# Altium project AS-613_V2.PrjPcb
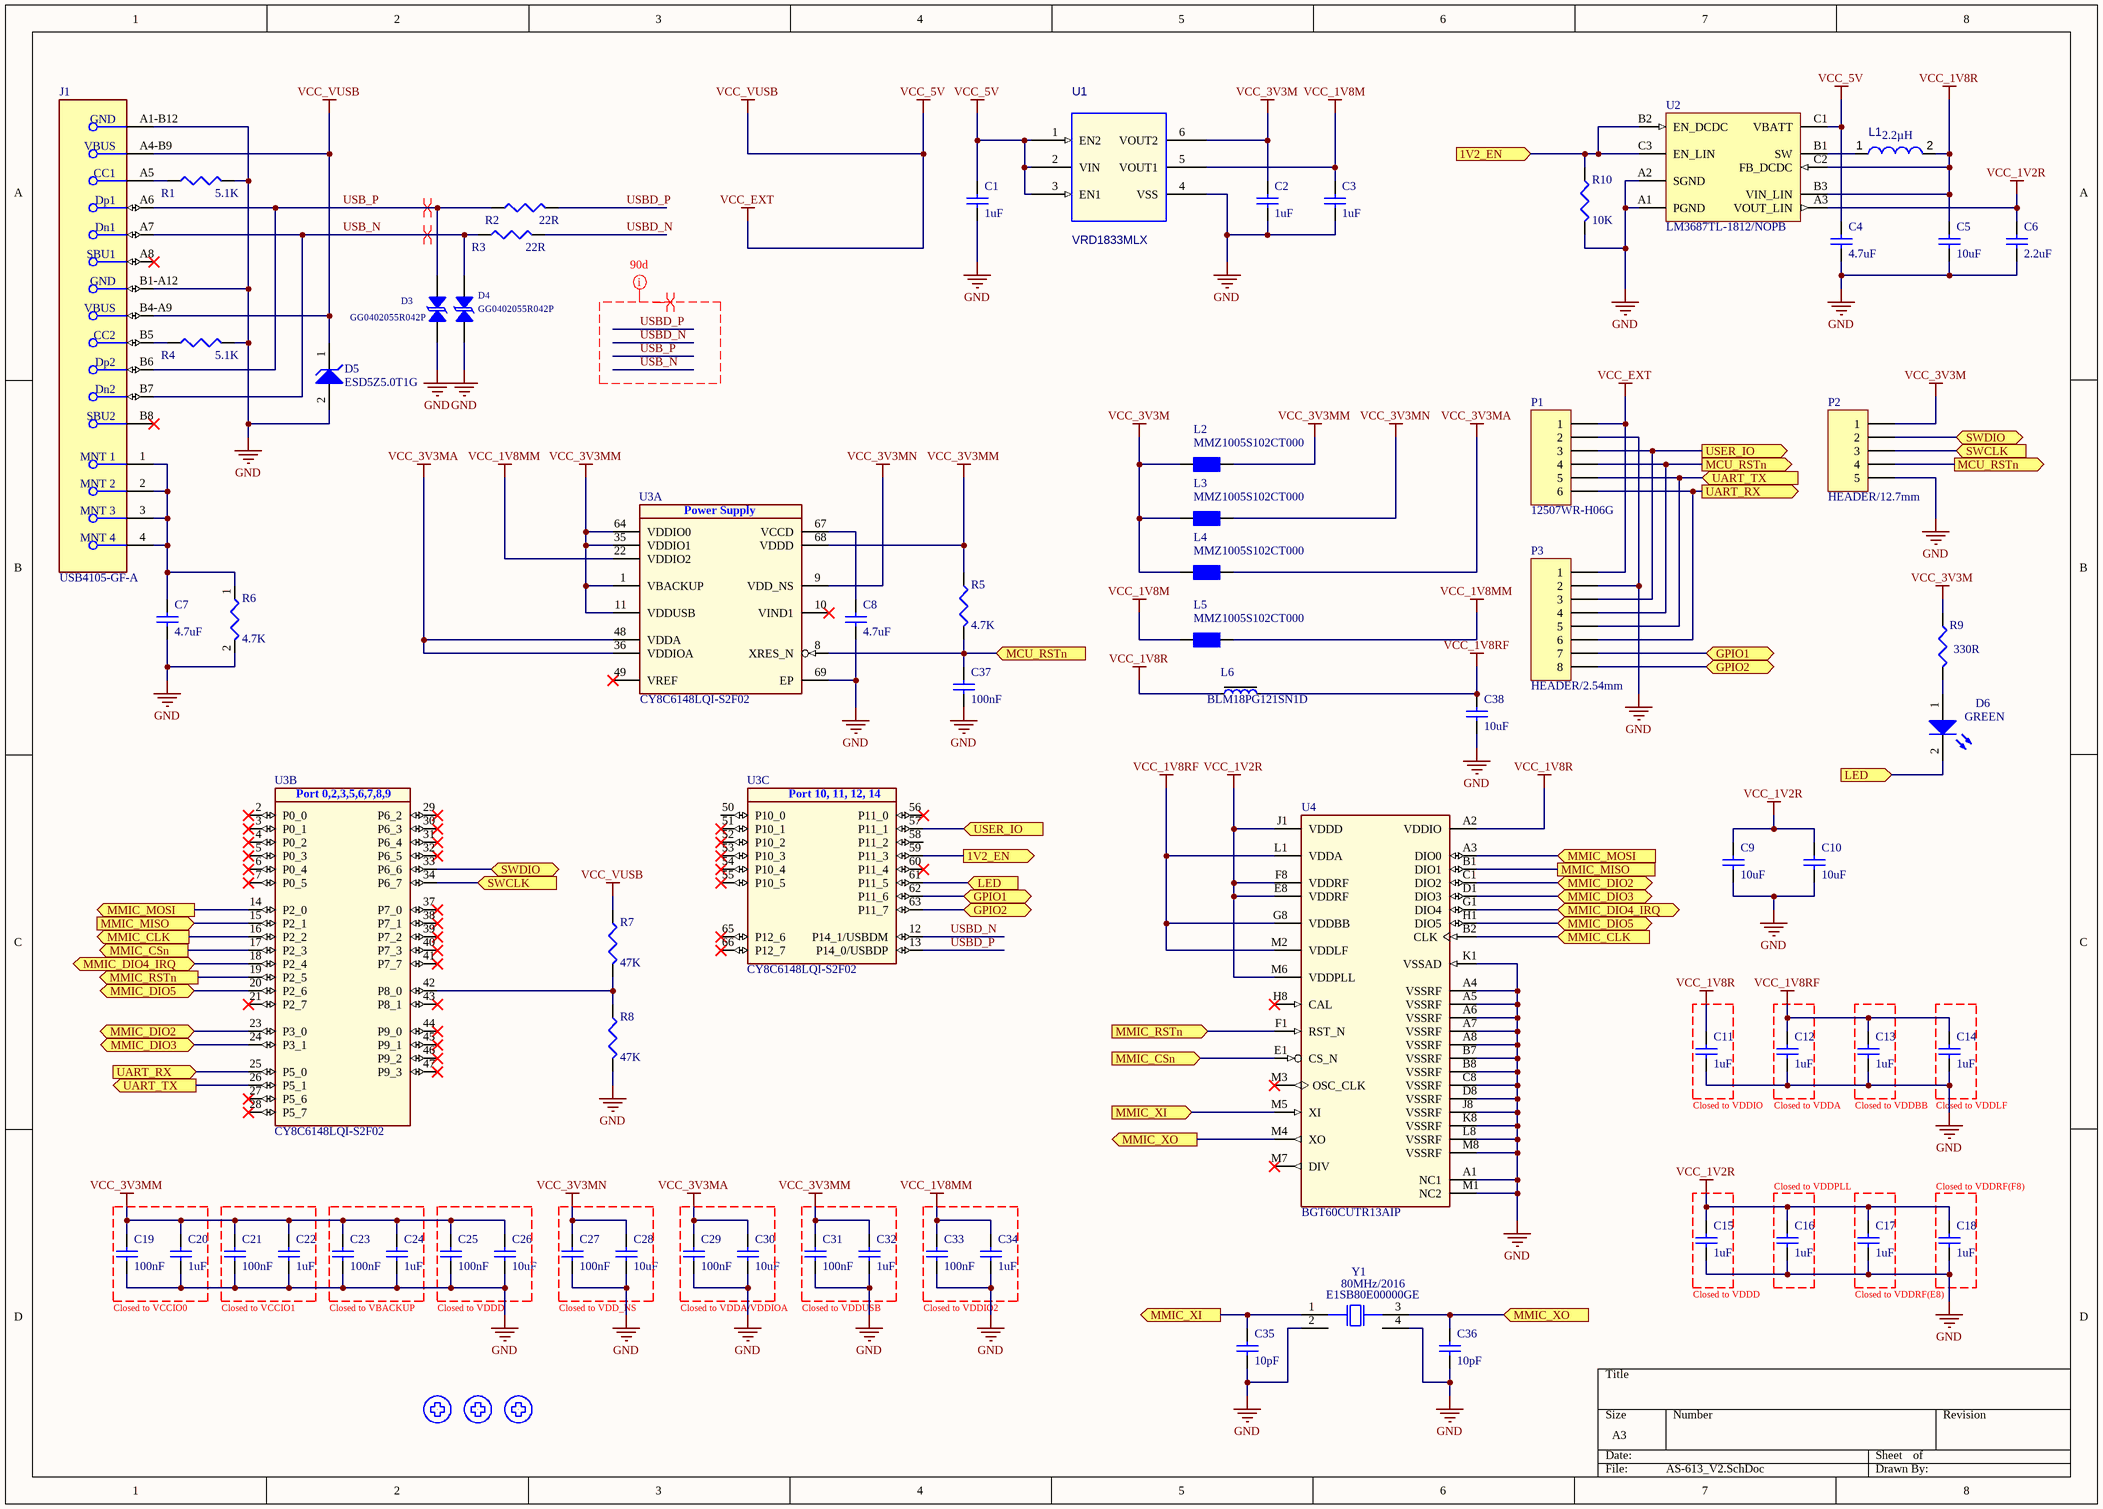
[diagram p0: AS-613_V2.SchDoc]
1 sheet, 70 parts. Net scope: flat (ports and power ports of the same name join across sheets).
Board file: AS-613V2.PcbDoc

## Sheet AS-613_V2.SchDoc
size A3; SheetNumber: 1; SheetTotal: 1; SPICEModelCacheAUYJBHOQ: <root> / <DocumentId>AUYJBHOQ</DocumentId> / <CacheFrame Number="0"> / <Model Name="cap" Kind="MDL"> / <Text>*Default semiconductor capacitor / .MODEL CAP C()</Text> / </Model> / </CacheFrame> / </root>

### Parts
C1  value 1uF  [CAP 0402/1005]  (hidden comment: Cap Semi)
C2  value 1uF  [CAP 0402/1005]  (hidden comment: Cap Semi)
C3  value 1uF  [CAP 0402/1005]  (hidden comment: Cap Semi)
C4  value 4.7uF  [CAP 0603/1608]  (hidden comment: Cap Semi)
C5  value 10uF  [CAP 0603/1608]  (hidden comment: Cap Semi)
C6  value 2.2uF  [CAP 0603/1608]  (hidden comment: Cap Semi)
C7  value 4.7uF  [CAP 0603/1608]  (hidden comment: Cap Semi)
C8  value 4.7uF  [CAP 0402/1005]  (hidden comment: Cap Semi)
C9  value 10uF  [CAP 0402/1005]  (hidden comment: Cap Semi)
C10  value 10uF  [CAP 0402/1005]  (hidden comment: Cap Semi)
C11  value 1uF  [CAP 0402/1005]  (hidden comment: Cap Semi)
C12  value 1uF  [CAP 0402/1005]  (hidden comment: Cap Semi)
C13  value 1uF  [CAP 0402/1005]  (hidden comment: Cap Semi)
C14  value 1uF  [CAP 0402/1005]  (hidden comment: Cap Semi)
C15  value 1uF  [CAP 0402/1005]  (hidden comment: Cap Semi)
C16  value 1uF  [CAP 0402/1005]  (hidden comment: Cap Semi)
C17  value 1uF  [CAP 0402/1005]  (hidden comment: Cap Semi)
C18  value 1uF  [CAP 0402/1005]  (hidden comment: Cap Semi)
C19  value 100nF  [CAP 0402/1005]  (hidden comment: Cap Semi)
C20  value 1uF  [CAP 0402/1005]  (hidden comment: Cap Semi)
C21  value 100nF  [CAP 0402/1005]  (hidden comment: Cap Semi)
C22  value 1uF  [CAP 0402/1005]  (hidden comment: Cap Semi)
C23  value 100nF  [CAP 0402/1005]  (hidden comment: Cap Semi)
C24  value 1uF  [CAP 0402/1005]  (hidden comment: Cap Semi)
C25  value 100nF  [CAP 0402/1005]  (hidden comment: Cap Semi)
C26  value 10uF  [CAP 0402/1005]  (hidden comment: Cap Semi)
C27  value 100nF  [CAP 0402/1005]  (hidden comment: Cap Semi)
C28  value 10uF  [CAP 0402/1005]  (hidden comment: Cap Semi)
C29  value 100nF  [CAP 0402/1005]  (hidden comment: Cap Semi)
C30  value 10uF  [CAP 0402/1005]  (hidden comment: Cap Semi)
C31  value 100nF  [CAP 0402/1005]  (hidden comment: Cap Semi)
C32  value 1uF  [CAP 0402/1005]  (hidden comment: Cap Semi)
C33  value 100nF  [CAP 0402/1005]  (hidden comment: Cap Semi)
C34  value 1uF  [CAP 0402/1005]  (hidden comment: Cap Semi)
C35  value 10pF  [CAP 0402/1005]  (hidden comment: Cap Semi)
C36  value 10pF  [CAP 0402/1005]  (hidden comment: Cap Semi)
C37  value 100nF  [CAP 0402/1005]  (hidden comment: Cap Semi)
C38  value 10uF  [CAP 0603/1608]  (hidden comment: Cap Semi)
D3  GG0402055R042P  [TVS 0402/1005 - BI]
D4  GG0402055R042P  [TVS 0402/1005 - BI]
D5  ESD5Z5.0T1G  [SOD523 - 21]
D6  GREEN  [LED 0603/1608 RED -21]
J1  USB4105-GF-A  [CON/ USB/ GCT_USB4105-GF-A]
L1  value 2.2µH  [IND 2520]  (hidden comment: VLS252010HBX-2R2M-1)
L2  MMZ1005S102CT000  [FER 0402/1005]
L3  MMZ1005S102CT000  [FER 0402/1005]
L4  MMZ1005S102CT000  [FER 0402/1005]
L5  MMZ1005S102CT000  [FER 0402/1005]
L6  BLM18PG121SN1D  [FER 0603/1608]
MT1  MOUNT HOLE  [MT-3 /HOLE]  (value not drawn)  (no BOM)
MT2  MOUNT HOLE  [MT-3 /HOLE]  (value not drawn)  (no BOM)
MT3  MOUNT HOLE  [MT-3 /HOLE]  (value not drawn)  (no BOM)
P1  12507WR-H06G  [12507WR-H06G]
P2  HEADER/12.7mm  [Pin Header 1x5 1.27mm]
P3  HEADER/2.54mm  [Pin Header 1x8 TH Pitch 2.54mm]
R1  value 5.1K  [RES 0402/1005]  (hidden comment: Res3)
R2  value 22R  [RES 0402/1005]  (hidden comment: Res3)
R3  value 22R  [RES 0402/1005]  (hidden comment: Res3)
R4  value 5.1K  [RES 0402/1005]  (hidden comment: Res3)
R5  value 4.7K  [RES 0402/1005]  (hidden comment: Res3)
R6  value 4.7K  [RES 0402/1005]  (hidden comment: Res3)
R7  value 47K  [RES 0402/1005]  (hidden comment: Res3)
R8  value 47K  [RES 0402/1005]  (hidden comment: Res3)
R9  value 330R  [RES 0402/1005]  (hidden comment: Res3)
R10  value 10K  [RES 0402/1005]  (hidden comment: Res3)
U1  VRD1833MLX  [LLP-6 / L2.0-W1.8-P0.50-BL-EP]
U2  LM3687TL-1812/NOPB  [DSBGA-9 / BGA50P147X147]
U3  CY8C6148LQI-S2F02  [QFN-68 /QFN40P800X800X100-69N]  (parts A,B,C of 3)
U4  BGT60CUTR13AIP  [BGT60CUTR13AIP / IFX- PG-VF2BGA-38-1]
Y1  80MHz/2016  value E1SB80E00000GE  [XTAL/2016]

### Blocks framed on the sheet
Closed to VDDPLL: C16
Closed to VDDRF(F8): C18

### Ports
1V2_EN (in), 1V2_EN (out), GPIO1 (bidir), GPIO2 (bidir), LED (in), MCU_RSTn (in), MCU_RSTn (out), MMIC_CLK (in), MMIC_CLK (out), MMIC_CSn (in), MMIC_CSn (out), MMIC_DIO2 (bidir), MMIC_DIO3 (bidir), MMIC_DIO4_IRQ (bidir), MMIC_DIO5 (bidir), MMIC_MISO, MMIC_MISO (in), MMIC_MOSI (in), MMIC_MOSI (out), MMIC_RSTn (in), MMIC_RSTn (out), MMIC_XI (in), MMIC_XI (out), MMIC_XO (in), MMIC_XO (out), SWCLK (in), SWDIO (bidir), UART_RX (in), UART_RX (out), UART_TX (in), UART_TX (out), USER_IO (in), USER_IO (out)

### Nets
GND: C1.1 C2.1 C3.1 C4.1 C5.1 C6.1 C7.1 C8.1 C9.1 C10.1 C11.1 C12.1 C13.1 C14.1 C15.1 C16.1 C17.1 C18.1 C19.1 C20.1 C21.1 C22.1 C23.1 C24.1 C25.1 C26.1 C27.1 C28.1 C29.1 C30.1 C31.1 C32.1 C33.1 C34.1 C35.1 C36.1 C37.1 C38.1 D3.1 D4.1 D5.2(A) J1.A1-B12(GND) J1.B1-A12(GND) P1.2 P2.5 P3.2 R1.2 R4.2 R6.2 R8.2 R10.2 U1.4(VSS) U2.A1(PGND) U2.A2(SGND) U3.69(EP) U4.A1(NC1) U4.A4(VSSRF) U4.A5(VSSRF) U4.A6(VSSRF) U4.A7(VSSRF) U4.A8(VSSRF) U4.B7(VSSRF) U4.B8(VSSRF) U4.C8(VSSRF) U4.D8(VSSRF) U4.J8(VSSRF) U4.K1(VSSAD) U4.K8(VSSRF) U4.L8(VSSRF) U4.M1(NC2) U4.M8(VSSRF) Y1.2 Y1.4
VCC_1V2R: C6.2 C9.2 C10.2 C15.2 C16.2 C17.2 C18.2 U2.A3(VOUT_LIN) U4.E8(VDDRF) U4.F8(VDDRF) U4.J1(VDDD) U4.M6(VDDPLL)
VCC_1V8M: C3.2 L5.1 U1.5(VOUT1)
VCC_1V8MM: C33.2 C34.2 L5.2 U3.22(VDDIO2)
VCC_1V8R: C5.2 C11.2 L1.2 L6.2 U2.B3(VIN_LIN) U2.C2(FB_DCDC) U4.A2(VDDIO)
VCC_1V8RF: C12.2 C13.2 C14.2 C38.2 L6.1 U4.G8(VDDBB) U4.L1(VDDA) U4.M2(VDDLF)
VCC_3V3M: C2.2 L2.1 L3.1 L4.1 P2.1 R9.1 U1.6(VOUT2)
VCC_3V3MA: C29.2 C30.2 L4.2 U3.36(VDDIOA) U3.48(VDDA)
VCC_3V3MM: C19.2 C20.2 C21.2 C22.2 C23.2 C24.2 C25.2 C26.2 C31.2 C32.2 L2.2 R5.1 U3.1(VBACKUP) U3.11(VDDUSB) U3.35(VDDIO1) U3.64(VDDIO0) U3.68(VDDD)
VCC_3V3MN: C27.2 C28.2 L3.2 U3.9(VDD_NS)
VCC_5V: C1.2 C4.2 D5.1(K) J1.A4-B9(VBUS) J1.B4-A9(VBUS) P1.1 P3.1 R7.1 U1.1(EN2) U1.2(VIN) U1.3(EN1) U2.C1(VBATT)  [also labelled VCC_EXT, VCC_VUSB]
1V2_EN: R10.1 U2.B2(EN_DCDC) U2.C3(EN_LIN) U3.59(P11_3) ; port 1V2_EN
GPIO1: P3.7 U3.62(P11_6) ; port GPIO1
GPIO2: P3.8 U3.63(P11_7) ; port GPIO2
LED: D6.2(K) U3.61(P11_5) ; port LED
MCU_RSTn: C37.2 P1.4 P2.4 P3.4 R5.2 U3.8(XRES_N) ; port MCU_RSTn
MMIC_CLK: U3.16(P2_2) U4.B2(CLK) ; port MMIC_CLK
MMIC_CSn: U3.17(P2_3) U4.E1(CS_N) ; port MMIC_CSn
MMIC_DIO2: U3.23(P3_0) U4.C1(DIO2) ; port MMIC_DIO2
MMIC_DIO3: U3.24(P3_1) U4.D1(DIO3) ; port MMIC_DIO3
MMIC_DIO4_IRQ: U3.18(P2_4) U4.G1(DIO4) ; port MMIC_DIO4_IRQ
MMIC_DIO5: U3.20(P2_6) U4.H1(DIO5) ; port MMIC_DIO5
MMIC_MISO: U3.15(P2_1) U4.B1(DIO1) ; port MMIC_MISO
MMIC_MOSI: U3.14(P2_0) U4.A3(DIO0) ; port MMIC_MOSI
MMIC_RSTn: U3.19(P2_5) U4.F1(RST_N) ; port MMIC_RSTn
MMIC_XI: C35.2 U4.M5(XI) Y1.1 ; port MMIC_XI
MMIC_XO: C36.2 U4.M4(XO) Y1.3 ; port MMIC_XO
SWCLK: P2.3 U3.34(P6_7) ; port SWCLK
SWDIO: P2.2 U3.33(P6_6) ; port SWDIO
UART_RX: P1.6 P3.6 U3.25(P5_0) ; port UART_RX
UART_TX: P1.5 P3.5 U3.26(P5_1) ; port UART_TX
USB_N: D4.2 J1.A7(Dn1) J1.B7(Dn2) R3.1
USB_P: D3.2 J1.A6(Dp1) J1.B6(Dp2) R2.1
USBD_N: R3.2 U3.12(P14_1/USBDM)
USBD_P: R2.2 U3.13(P14_0/USBDP)
USER_IO: P1.3 P3.3 U3.57(P11_1) ; port USER_IO
NetC7_2: C7.2 J1.1(MNT_1) J1.2(MNT_2) J1.3(MNT_3) J1.4(MNT_4) R6.1
NetC8_2: C8.2 U3.67(VCCD)
NetD6_1: D6.1(A) R9.2
NetJ1_A5: J1.A5(CC1) R1.1
NetJ1_B5: J1.B5(CC2) R4.1
NetL1_1: L1.1 U2.B1(SW)
NetR7_2: R7.2 R8.1 U3.42(P8_0)

Not connected (* = marked no-connect by the designer): J1 A8(SBU1)* B8(SBU2)*; MT1 1; MT2 1; MT3 1; U3 2(P0_0)* 3(P0_1)* 4(P0_2)* 5(P0_3)* 6(P0_4)* 7(P0_5)* 10(VIND1)* 21(P2_7)* 27(P5_6)* 28(P5_7)* 29(P6_2)* 30(P6_3)* 31(P6_4)* 32(P6_5)* 37(P7_0)* 38(P7_1)* 39(P7_2)* 40(P7_3)* 41(P7_7)* 43(P8_1)* 44(P9_0)* 45(P9_1)* 46(P9_2)* 47(P9_3)* 49(VREF)* 50(P10_0) 51(P10_1)* 52(P10_2)* 53(P10_3)* 54(P10_4)* 55(P10_5)* 56(P11_0)* 58(P11_2) 60(P11_4)* 65(P12_6)* 66(P12_7)*; U4 H8(CAL)* M3(OSC_CLK)* M7(DIV)*

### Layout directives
differential pair: USB_N, USB_P, USBD_N, USBD_P
net class 90d: USB_N, USB_P, USBD_N, USBD_P

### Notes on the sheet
- Closed to VDDIO
- Closed to VDDA
- Closed to VDDBB
- (near C14) Closed to VDDLF
- Closed to VCCIO0
- Closed to VCCIO1
- Closed to VBACKUP
- Closed to VDDD
- Closed to VDD_NS
- Closed to VDDA/VDDIOA
- Closed to VDDUSB
- Closed to VDDIO2
- Closed to VDDRF(E8)

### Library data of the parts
C1-C38 = Cap Semi: Capacitor (Semiconductor SIM Model)
D3 D4 = TVS Diode_BI: TVS Diode Bi-Directional
D5 = ONSC-K1A2-2: Transient Voltage Suppressor, Micro-Packaged Diode for ESD Protection, 2-Pin SOD-523, Pb-Free, Tape and Reel; Manufacturer: On Semiconductor; V(BR) Min (V): 6.2; VRWM Max (V): 5; Number of Lines: 1; PPK Max (W): 174; IR Max (uA): 0.05; Direction: Unidirectional
D6 = LED2: Typical RED, GREEN, YELLOW, AMBER GaAs LED
J1 = e7c17a616881a82b79941196b4bec10: CONN RCPT USB2.0 TYPEC 5A; Manufacturer: GCT; Voltage Rating: 20V; Is Female: yes; Current Rating: 5/6.25/1.25/0.25A; Number Of Contacts: 16; Conn Orientation: Right Angle
L1 = CMP-001-0020-1: Inductor for Power Circuit, 2.2 uH, +/- 20%, -40 to 105 degC, 2-Pin SMD, RoHS, Tape and Reel
L2-L5 = INDUCTOR1: SMD Ferrite Bead; Preis: 0; Hersteller: Würth
L6 = FB0402-120R@100M-500mA: Ferrite Bead; Manufacturer: Murata; Manufacturer Part Number: BLM15AG121SN1D; Part number IPS: 00000009954; Note: Chip EMIFIL Inductor Type Chip Ferrite Bead; Artikkelnr Noca: 33029317
MT1-MT3 = Mount Bolt
P1 = Header 6: Header, 6-Pin
P2 = Header 5: Header, 5-Pin
P3 = Header 8: Header, 8-Pin
R1-R10 = Res3: Resistor
U1 = VRD1833MLX: Part Reference: U1
U2 = PM-DCDC-LM3687-9: Step-Down DC-DC Converter with Integrated Low Dropout Regulator and Startup Mode, 9-pin Micro SMD, Pb-Free; Manufacturer: Texas Instruments; PackageTopMarking: XV*I SB; High-Reliability: Y; PowerWise: N; CompType: MiscPower
U3 = CY8C6148LQI-S2F02: 32-bit PSoC 6 Arm Cortex-M4/M0+ MCU; Manufacturer: Infineon Technologies
U4 = BGT60CUTR13AIP: Multiple Parts: No; Manufacturer: Infineon Technologies; Product Name: IFX_BGT60CUTR13AIP; Pins Electrical: 38; Component Height [mm]: 0.86; Component Height (max.)  [mm]: 0.91; PLM Status: Preliminary
Y1 = 801566: Crystal, Automotive & Industrial Grade Ceramic Base SMD; Manufacturer: Abracon Corporation; Manufacturer Order Number: ABM8AIG-40.000MHZ-12-2Z-T3; Symbol type: Standard Crystal Symbol, 4 Pins; Article Number: 801566; Version Number: V00; Tolerance Neg: -20%; Tolerance Pos: 20%; Combined Parameters: WLAN Standard Crystal;Tol.:--20%/+20%; QuickPick: 40000000 / Crystal; Style: Standard; Automotive Qualified: AEC Q200; ComponentStatus: Released; PLMStatus: Active; Second Source allowed: Yes; Voltage DC (max): na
